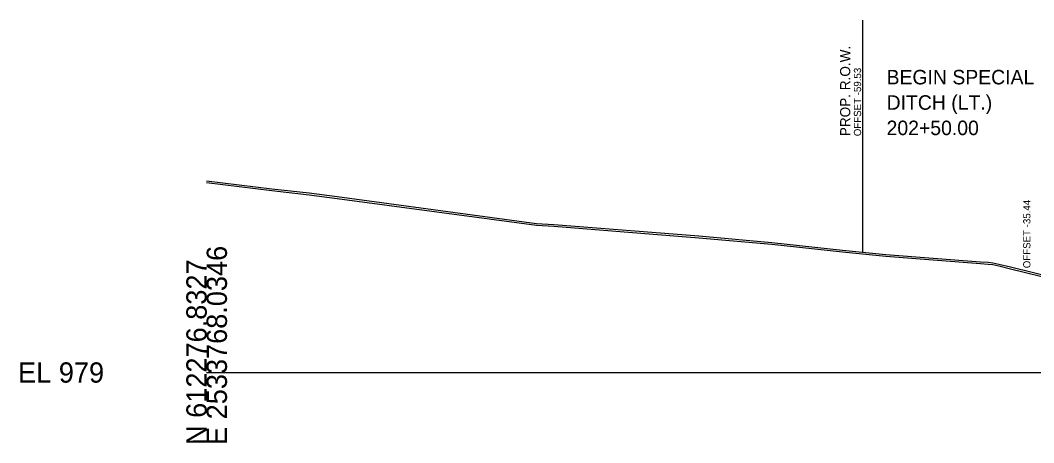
# Model space of a CAD drawing. Extents: x -120 to 2876, y -25 to 8560.
# Drawn here: x -25.7 to 114, y 4990.3 to 5048.6 of the extents above; entities that cross this region are included whole.
import ezdxf

# ---------------------------------------------------------------- set-up
doc = ezdxf.new("R2010")
doc.units = 0
for name, color, linetype in [('DESIGN - ROW - Right-of-Way and Easement Labels', 7, 'Continuous'), ('DESIGN - ROW - Right-of-Way Linework', 7, 'Continuous'), ('DESIGN - SHEET - Light Grid', 7, 'Continuous'), ('DESIGN - TRANSPORTATION - Text', 7, 'Continuous'), ('DESIGN - TYPICAL - Slope Tie Text', 7, 'Continuous'), ('SURVEY - GROUND - Bottom of Topsoil Layer', 7, 'Continuous'), ('SURVEY - GROUND - Top of Ground', 7, 'Continuous')]:
    doc.layers.add(name, color=color, linetype=linetype)

msp = doc.modelspace()

# ---------------------------------------------------------------- linework, layer by layer
at = {"layer": 'DESIGN - ROW - Right-of-Way Linework'}
msp.add_line((90.47, 5016.61), (90.47, 5048.61), dxfattribs=at)
at = {"layer": 'DESIGN - SHEET - Light Grid'}
msp.add_line((0, 5000), (150, 5000), dxfattribs=at)
at = {"layer": 'SURVEY - GROUND - Bottom of Topsoil Layer'}
for p, q in [((0, 5026.22), (8.98, 5025.12)), ((8.98, 5025.12), (14.14, 5024.53)), ((14.14, 5024.53), (18.01, 5024.02)), ((18.01, 5024.02), (45.47, 5020.33)), ((45.47, 5020.33), (47.87, 5020.18)), ((47.87, 5020.18), (67.83, 5018.6)), ((67.83, 5018.6), (77.92, 5017.7)), ((77.92, 5017.7), (87.65, 5016.64)), ((87.65, 5016.64), (93.65, 5016.05)), ((93.65, 5016.05), (106.69, 5015.03)), ((106.69, 5015.03), (107.72, 5014.96)), ((107.72, 5014.96), (108.39, 5014.89)), ((108.39, 5014.89), (109.2, 5014.71)), ((109.2, 5014.71), (110.79, 5014.32)), ((110.79, 5014.32), (137.29, 5007.78))]:
    msp.add_line(p, q, dxfattribs=at)
at = {"layer": 'SURVEY - GROUND - Top of Ground'}
msp.add_lwpolyline([(0, 5026.47), (8.98, 5025.37), (14.14, 5024.78), (18.01, 5024.27), (45.47, 5020.58), (47.87, 5020.43), (67.83, 5018.85), (77.92, 5017.95), (87.65, 5016.89), (93.65, 5016.3), (106.69, 5015.28), (107.72, 5015.21), (108.39, 5015.14), (109.2, 5014.96), (110.79, 5014.57), (137.29, 5008.03)], dxfattribs=at)

# ---------------------------------------------------------------- texts
at = {"layer": 'DESIGN - ROW - Right-of-Way and Easement Labels'}
for s, height, p in [('PROP. R.O.W.', 1.4, (88.72, 5032.61)), ('OFFSET -59.53', 1, (90.22, 5032.61))]:
    msp.add_text(s, height=height, rotation=90, dxfattribs=at).set_placement(p)
at = {"layer": 'DESIGN - SHEET - Light Grid'}
for s, p in [('E 2533768.0346', (2.8, 4990)), ('N 612276.8327', (0, 4990))]:
    msp.add_text(s, height=2.8, rotation=90, dxfattribs=at).set_placement(p)
msp.add_text('EL 979', height=2.8, dxfattribs=at).set_placement((-26, 4998.6))
at = {"layer": 'DESIGN - TRANSPORTATION - Text'}
for s, p in [('BEGIN SPECIAL ', (93.73, 5039.76)), ('DITCH (LT.)', (93.73, 5036.26)), ('202+50.00', (93.73, 5032.76))]:
    msp.add_text(s, height=2, dxfattribs=at).set_placement(p)
at = {"layer": 'DESIGN - TYPICAL - Slope Tie Text'}
msp.add_text('OFFSET -35.44', height=1, rotation=90, dxfattribs=at).set_placement((113.56, 5014.39))

doc.saveas('drawing.dxf')
